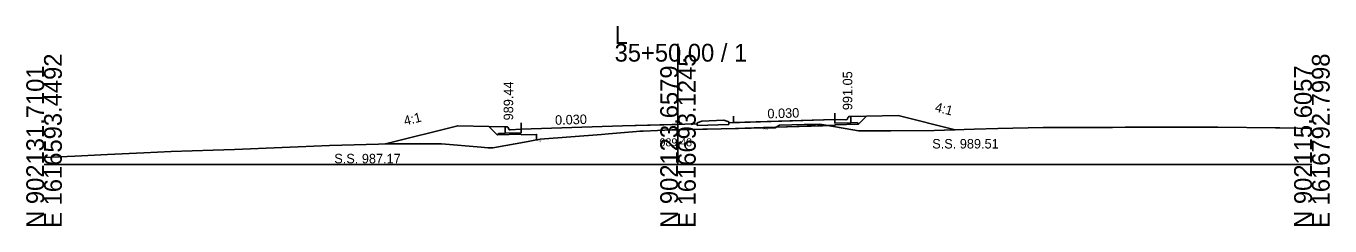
# Model space of a CAD drawing. Extents: x 1009 to 7438, y -1586 to 7964.
# Drawn here: x 3032.1 to 3237.7, y 3414 to 3445.5 of the extents above; entities that cross this region are included whole.
import ezdxf

# ---------------------------------------------------------------- set-up
doc = ezdxf.new("R2010")
doc.units = 0
for name, color, linetype in [('Exist Cross Section Cell', 7, 'Continuous'), ('Exist XS Center Line Elevation Label', 7, 'Continuous'), ('Exist XS Ground Line', 7, 'Continuous'), ('Prop XS Dump Level', 7, 'Continuous'), ('Prop XS Earthwork Shape', 7, 'Continuous'), ('Prop XS EOT Tick Mark', 7, 'Continuous'), ('Prop XS Finish Grade', 7, 'Continuous'), ('Prop XS Finish Grade CurbGutter', 7, 'Continuous'), ('Prop XS Finish Grade Earthwork', 7, 'Continuous'), ('Prop XS Finish Grade Pavement', 7, 'Continuous'), ('Prop XS Hydro Elevations', 7, 'Continuous'), ('Prop XS Pvmt Edge Slope', 7, 'Continuous'), ('Prop XS SE Text', 7, 'Continuous'), ('Prop XS Side Slope Text', 7, 'Continuous'), ('Prop XS SS Elevation Text', 7, 'Continuous'), ('Prop XS Subgrade CurbGutter', 7, 'Continuous'), ('Prop XS Subgrade Earthwork', 7, 'Continuous')]:
    doc.layers.add(name, color=color, linetype=linetype)

msp = doc.modelspace()

# ---------------------------------------------------------------- linework, layer by layer
at = {"layer": 'Exist Cross Section Cell'}
for p, q in [((3134.89, 3423.73), (3134.89, 3442.74)), ((3034.89, 3423.73), (3134.89, 3423.73)), ((3134.89, 3423.73), (3234.89, 3423.73))]:
    msp.add_line(p, q, dxfattribs=at)
at = {"layer": 'Exist XS Ground Line'}
for p, q in [((3123.93, 3428.56), (3128.36, 3428.93)), ((3128.36, 3428.93), (3128.87, 3428.97)), ((3128.87, 3428.97), (3129.39, 3428.99)), ((3129.39, 3428.99), (3133.93, 3429.19)), ((3133.93, 3429.19), (3134.89, 3429.21)), ((3134.89, 3429.21), (3138.81, 3429.29)), ((3138.81, 3429.29), (3139.49, 3429.3)), ((3139.49, 3429.3), (3148.38, 3429.49)), ((3148.38, 3429.49), (3148.78, 3429.49)), ((3148.78, 3429.49), (3150.23, 3429.48)), ((3150.23, 3429.48), (3150.88, 3429.94)), ((3150.88, 3429.94), (3154.81, 3430)), ((3154.81, 3430), (3155.88, 3430.03)), ((3155.88, 3430.03), (3156.6, 3430.03)), ((3156.6, 3430.03), (3157.26, 3430.07)), ((3157.26, 3430.07), (3161.26, 3429.38)), ((3161.26, 3429.38), (3163.34, 3429.04)), ((3163.34, 3429.04), (3168.45, 3429.03)), ((3168.45, 3429.03), (3175.31, 3429.09)), ((3175.31, 3429.09), (3181.61, 3429.27)), ((3181.61, 3429.27), (3185.35, 3429.39)), ((3185.35, 3429.39), (3192.52, 3429.57)), ((3192.52, 3429.57), (3195.38, 3429.55)), ((3195.38, 3429.55), (3203.44, 3429.55)), ((3203.44, 3429.55), (3205.41, 3429.61)), ((3205.41, 3429.61), (3214.35, 3429.62)), ((3214.35, 3429.62), (3215.45, 3429.63)), ((3215.45, 3429.63), (3220.03, 3429.58)), ((3220.03, 3429.58), (3229.16, 3429.5)), ((3229.16, 3429.5), (3229.84, 3429.5)), ((3229.84, 3429.5), (3232.63, 3429.43)), ((3232.63, 3429.43), (3234.89, 3429.39)), ((3074.98, 3426.5), (3079.93, 3426.69)), ((3079.93, 3426.69), (3089.57, 3427)), ((3089.57, 3427), (3092.12, 3427)), ((3092.12, 3427), (3094.37, 3427)), ((3094.37, 3427), (3096.47, 3426.97)), ((3096.47, 3426.97), (3097.58, 3426.97)), ((3097.58, 3426.97), (3103.83, 3426.46)), ((3105.66, 3426.37), (3111.26, 3427.37)), ((3111.26, 3427.37), (3112.56, 3427.6)), ((3112.56, 3427.6), (3113.17, 3427.7)), ((3113.17, 3427.7), (3122.8, 3428.47)), ((3122.8, 3428.47), (3123.93, 3428.56)), ((3034.89, 3424.81), (3039.72, 3425.04)), ((3039.72, 3425.04), (3044.88, 3425.27)), ((3044.88, 3425.27), (3050.63, 3425.55)), ((3050.63, 3425.55), (3054.92, 3425.77)), ((3054.92, 3425.77), (3061.54, 3425.97)), ((3061.54, 3425.97), (3064.95, 3426.08)), ((3064.95, 3426.08), (3072.46, 3426.4)), ((3072.46, 3426.4), (3074.98, 3426.5)), ((3103.83, 3426.46), (3104.91, 3426.37)), ((3104.91, 3426.37), (3105.66, 3426.37))]:
    msp.add_line(p, q, dxfattribs=at)
at = {"layer": 'Prop XS Dump Level'}
for p, q in [((3143.64, 3430.32), (3159.64, 3430.8)), ((3143.64, 3430.32), (3159.64, 3430.8)), ((3110.14, 3429.31), (3126.14, 3429.79)), ((3110.14, 3429.31), (3126.14, 3429.79)), ((3126.14, 3429.79), (3134.89, 3430.05)), ((3126.14, 3429.79), (3134.89, 3430.05))]:
    msp.add_line(p, q, dxfattribs=at)
at = {"layer": 'Prop XS Earthwork Shape'}
for points in [[(3175.31, 3429.09), (3178.63, 3429.19), (3169.64, 3431.43), (3164.64, 3431.33), (3163.39, 3430.08), (3159.64, 3429.97), (3159.64, 3429.88), (3158.54, 3429.85), (3161.26, 3429.38), (3163.34, 3429.04), (3168.45, 3429.03)], [(3110.14, 3428.39), (3110.14, 3428.48), (3106.39, 3428.37), (3105.04, 3429.73), (3100.14, 3429.83), (3088.74, 3426.98), (3089.57, 3427), (3092.12, 3427), (3094.37, 3427), (3096.47, 3426.97), (3097.58, 3426.97), (3103.83, 3426.46), (3104.91, 3426.37), (3105.66, 3426.37), (3111.26, 3427.37), (3112.56, 3427.6), (3112.59, 3427.6), (3112.59, 3428.47)], [(3142.49, 3429.36), (3148.38, 3429.49), (3148.38, 3429.54)], [(3148.38, 3429.54), (3150.4, 3429.6), (3150.23, 3429.48), (3148.78, 3429.49), (3148.38, 3429.49)], [(3154.81, 3430), (3155.88, 3430.03), (3156.6, 3430.03), (3157.26, 3430.07), (3158.54, 3429.85), (3150.4, 3429.6), (3150.88, 3429.94)]]:
    msp.add_lwpolyline(points, close=True, dxfattribs=at)
at = {"layer": 'Prop XS EOT Tick Mark'}
for p, q in [((3134.89, 3430.05), (3134.89, 3431.05)), ((3143.64, 3430.32), (3143.64, 3431.32)), ((3159.64, 3430.8), (3159.64, 3431.8)), ((3110.14, 3429.31), (3110.14, 3430.31))]:
    msp.add_line(p, q, dxfattribs=at)
at = {"layer": 'Prop XS Finish Grade'}
for p, q in [((3162.14, 3431.28), (3164.64, 3431.33)), ((3107.64, 3429.67), (3105.04, 3429.73))]:
    msp.add_line(p, q, dxfattribs=at)
at = {"layer": 'Prop XS Finish Grade CurbGutter'}
for p, q in [((3159.64, 3430.8), (3161.39, 3430.78)), ((3161.39, 3430.78), (3161.52, 3430.8)), ((3161.52, 3430.8), (3161.61, 3430.89)), ((3161.61, 3430.89), (3161.68, 3431.14)), ((3161.68, 3431.14), (3161.77, 3431.23)), ((3161.89, 3431.28), (3161.77, 3431.23)), ((3162.14, 3431.28), (3161.89, 3431.28)), ((3107.64, 3429.67), (3107.89, 3429.67)), ((3107.89, 3429.67), (3108.02, 3429.64)), ((3108.11, 3429.55), (3108.02, 3429.64)), ((3108.18, 3429.3), (3108.11, 3429.55)), ((3108.27, 3429.21), (3108.18, 3429.3)), ((3108.39, 3429.19), (3108.27, 3429.21)), ((3110.14, 3429.31), (3108.39, 3429.19)), ((3137.89, 3430.31), (3138.64, 3430.56)), ((3137.89, 3430.14), (3137.89, 3430.31)), ((3138.64, 3430.56), (3142.14, 3430.71)), ((3142.89, 3430.46), (3142.14, 3430.71)), ((3142.89, 3430.29), (3142.89, 3430.46))]:
    msp.add_line(p, q, dxfattribs=at)
at = {"layer": 'Prop XS Finish Grade Earthwork'}
for p, q in [((3164.64, 3431.33), (3169.64, 3431.43)), ((3169.64, 3431.43), (3178.63, 3429.19)), ((3100.14, 3429.83), (3088.74, 3426.98)), ((3105.04, 3429.73), (3100.14, 3429.83))]:
    msp.add_line(p, q, dxfattribs=at)
at = {"layer": 'Prop XS Finish Grade Pavement'}
for p, q in [((3142.89, 3430.29), (3159.64, 3430.8)), ((3110.14, 3429.31), (3126.14, 3429.79)), ((3126.14, 3429.79), (3137.89, 3430.14))]:
    msp.add_line(p, q, dxfattribs=at)
at = {"layer": 'Prop XS Pvmt Edge Slope'}
for p, q in [((3162.14, 3430.29), (3163.14, 3430.32)), ((3163.14, 3430.32), (3163.39, 3430.08)), ((3106.64, 3428.63), (3106.39, 3428.37)), ((3107.64, 3428.66), (3106.64, 3428.63))]:
    msp.add_line(p, q, dxfattribs=at)
at = {"layer": 'Prop XS Subgrade CurbGutter'}
for p, q in [((3159.64, 3430.8), (3159.64, 3430.22)), ((3162.14, 3430.29), (3162.14, 3431.28)), ((3107.64, 3428.66), (3107.64, 3429.67)), ((3110.14, 3428.73), (3107.64, 3428.66)), ((3110.14, 3429.31), (3110.14, 3428.73)), ((3137.89, 3430.14), (3137.89, 3429.89)), ((3137.89, 3429.89), (3142.89, 3430.04)), ((3142.89, 3430.29), (3142.89, 3430.04)), ((3159.64, 3430.22), (3162.14, 3430.29))]:
    msp.add_line(p, q, dxfattribs=at)
at = {"layer": 'Prop XS Subgrade Earthwork'}
for p, q in [((3163.39, 3430.08), (3164.64, 3431.33)), ((3106.39, 3428.37), (3105.04, 3429.73)), ((3148.38, 3429.54), (3142.49, 3429.36)), ((3148.38, 3429.54), (3159.64, 3429.88)), ((3148.38, 3429.54), (3148.38, 3429.49)), ((3148.38, 3429.54), (3148.38, 3429.49)), ((3159.64, 3429.97), (3163.39, 3430.08)), ((3159.64, 3429.88), (3159.64, 3429.97)), ((3110.14, 3428.48), (3106.39, 3428.37)), ((3110.14, 3428.39), (3110.14, 3428.48)), ((3112.59, 3428.47), (3110.14, 3428.39)), ((3112.59, 3428.47), (3112.59, 3427.6))]:
    msp.add_line(p, q, dxfattribs=at)

# ---------------------------------------------------------------- texts
at = {"layer": 'Exist Cross Section Cell'}
for s, p in [('L', (3124.89, 3442.74)), ('35+50.00 / 1', (3124.89, 3439.94))]:
    msp.add_text(s, height=2.8, dxfattribs=at).set_placement(p)
for s, p in [('E 1616693.1245', (3137.69, 3413.73)), ('N 902131.7101', (3034.89, 3413.73)), ('E 1616593.4492', (3037.69, 3413.73)), ('N 902123.6579', (3134.89, 3413.73)), ('N 902115.6057', (3234.89, 3413.73)), ('E 1616792.7998', (3237.69, 3413.73))]:
    msp.add_text(s, height=2.8, rotation=90, dxfattribs=at).set_placement(p)
at = {"layer": 'Exist XS Center Line Elevation Label'}
msp.add_text('989.48', height=1.25, dxfattribs=at).set_placement((3131.99, 3426.59))
at = {"layer": 'Prop XS Dump Level'}
for p in [(3148.38, 3429.19), (3148.38, 3429.19), (3148.38, 3429.19), (3112.59, 3427.3)]:
    msp.add_text('Eop', height=0.3, dxfattribs=at).set_placement(p)
at = {"layer": 'Prop XS Hydro Elevations'}
for s, p in [('991.05', (3162.39, 3432.28)), ('989.44', (3108.89, 3430.67))]:
    msp.add_text(s, height=1.5, rotation=90, dxfattribs=at).set_placement(p)
at = {"layer": 'Prop XS SE Text'}
for p in [(3115.52, 3429.97), (3149.02, 3430.98)]:
    msp.add_text('0.030', height=1.5, rotation=1.7184, dxfattribs=at).set_placement(p)
at = {"layer": 'Prop XS Side Slope Text'}
for rotation, p in [(345.9638, (3175.32, 3432.1)), (14.0362, (3091.83, 3429.84))]:
    msp.add_text('4:1', height=1.5, rotation=rotation, dxfattribs=at).set_placement(p)
at = {"layer": 'Prop XS SS Elevation Text'}
for s, p in [('S.S. 989.51', (3175, 3426.24)), ('S.S. 987.17', (3080.67, 3423.9))]:
    msp.add_text(s, height=1.5, dxfattribs=at).set_placement(p)

doc.saveas('drawing.dxf')
